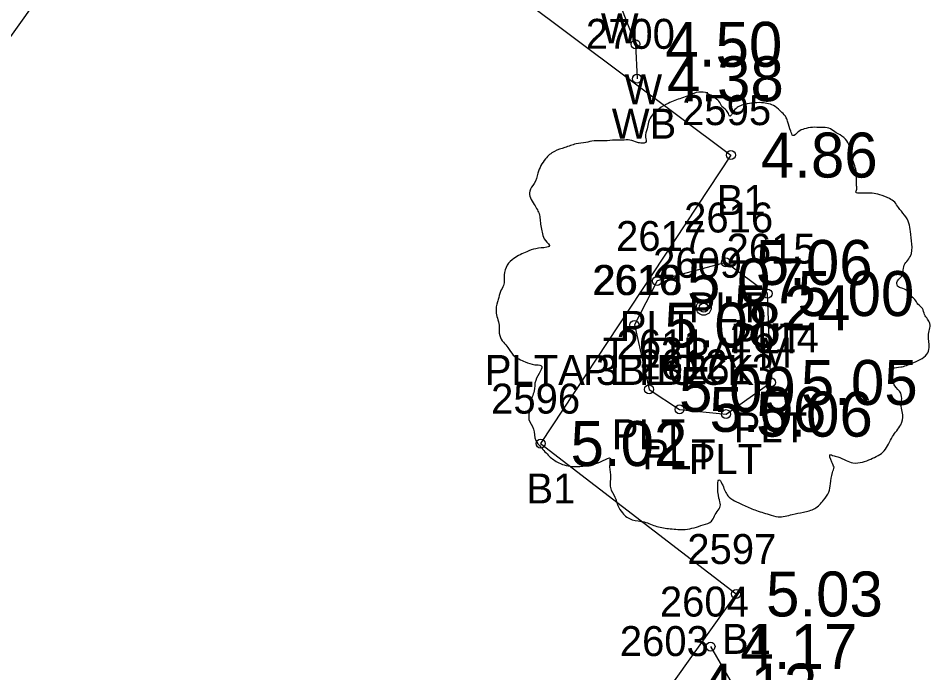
# Model space of a CAD drawing. Extents: x 2608598 to 2610682, y 641451 to 643526.
# Drawn here: x 2610088.05 to 2610118.53, y 642038.34 to 642060.19 of the extents above; entities that cross this region are included whole.
import ezdxf

# ---------------------------------------------------------------- set-up
doc = ezdxf.new("R2010")
doc.units = 0
for name, color, linetype in [('RD_EX_Bldg', 7, 'Continuous'), ('RD_EX_Bldg_txCode', 7, 'Continuous'), ('RD_EX_BldgApp', 7, 'Continuous'), ('RD_EX_BldgApp_txCode', 7, 'Continuous'), ('RD_EX_Conc_txCode', 7, 'Continuous'), ('RD_EX_Misc_txCode', 7, 'Continuous'), ('RD_EX_TX_Bldg_ELEV', 7, 'Continuous'), ('RD_EX_TX_BldgApp_ELEV', 7, 'Continuous'), ('RD_EX_TX_Conc_ELEV', 7, 'Continuous'), ('RD_EX_TX_Misc_ELEV', 7, 'Continuous'), ('RD_EX_TX_VEG_ELEV', 7, 'Continuous'), ('RD_EX_VEG', 7, 'Continuous'), ('RD_EX_VEG_txCode', 7, 'Continuous'), ('RD_SMD_Locator', 7, 'Continuous')]:
    doc.layers.add(name, color=color, linetype=linetype)

msp = doc.modelspace()

# ---------------------------------------------------------------- linework, layer by layer
at = {"layer": 'RD_EX_Bldg'}
msp.add_lwpolyline([(2610053.59, 642011.651), (2610094.327, 642068.736), (2610111.856, 642055.619), (2610105.498, 642045.99), (2610112.03, 642040.97), (2610078.047, 641993.35), (2610053.59, 642011.651)], dxfattribs=at)
at = {"layer": 'RD_EX_BldgApp'}
for points in [[(2610092.084, 642091.554), (2610090.066, 642087.454), (2610090.275, 642082.315), (2610090.442, 642078.076), (2610089.742, 642075.92), (2610088.411, 642073.718), (2610088.053, 642071.968), (2610088.518, 642070.915), (2610090.02, 642069.577), (2610091.576, 642069.053), (2610094.413, 642069.93), (2610096.189, 642069.722), (2610098.402, 642068.736), (2610102.184, 642065.332), (2610105.016, 642063.884), (2610107.881, 642061.348), (2610108.669, 642059.316), (2610108.72, 642058.165)], [(2610108.633, 642049.948), (2610109.123, 642047.799), (2610110.139, 642047.131), (2610111.694, 642046.972), (2610113.193, 642048.03), (2610113.081, 642050.997), (2610111.687, 642052.035), (2610109.389, 642051.418), (2610108.633, 642049.948)], [(2610111.175, 642039.216), (2610113.596, 642035.061)]]:
    msp.add_lwpolyline(points, dxfattribs=at)
at = {"layer": 'RD_EX_VEG'}
for centre, radius in [((2610110.949, 642050.524), 0.25), ((2610110.937, 642050.506), 0.0001)]:
    msp.add_circle(centre, radius, dxfattribs=at)
for points in [[(2610111.081, 642057.692), (2610110.781, 642057.717), (2610110.457, 642057.617), (2610110.207, 642057.517), (2610109.982, 642057.442), (2610109.757, 642057.342), (2610109.457, 642057.167), (2610109.232, 642056.967), (2610109.107, 642056.717), (2610109.057, 642056.492), (2610109.007, 642056.217), (2610109.007, 642056.042), (2610108.882, 642056.017), (2610108.732, 642056.042), (2610108.482, 642056.117), (2610108.232, 642056.117), (2610107.983, 642056.117), (2610107.633, 642056.092), (2610107.283, 642056.092), (2610107.008, 642056.042), (2610106.683, 642055.992), (2610106.308, 642055.867), (2610105.958, 642055.742), (2610105.659, 642055.493), (2610105.409, 642055.018), (2610105.284, 642054.668), (2610105.134, 642054.418), (2610105.284, 642053.968), (2610105.459, 642053.618), (2610105.484, 642053.418), (2610105.559, 642052.994), (2610105.659, 642052.769), (2610105.784, 642052.569), (2610105.709, 642052.544), (2610105.334, 642052.494), (2610105.034, 642052.394), (2610104.609, 642052.169), (2610104.384, 642051.944), (2610104.284, 642051.619), (2610104.259, 642051.269), (2610104.159, 642051.07), (2610104.084, 642050.795), (2610104.059, 642050.72), (2610104.009, 642050.395), (2610104.109, 642049.945), (2610104.134, 642049.595), (2610104.259, 642049.37), (2610104.409, 642049.195), (2610104.584, 642048.945), (2610104.984, 642048.721), (2610105.309, 642048.621), (2610105.509, 642048.596), (2610105.334, 642048.096), (2610105.284, 642047.746), (2610105.159, 642047.346), (2610105.159, 642047.271), (2610105.109, 642046.796), (2610105.259, 642046.471), (2610105.334, 642046.097), (2610105.509, 642045.872), (2610105.784, 642045.572), (2610106.108, 642045.347), (2610106.608, 642045.222), (2610107.008, 642045.247), (2610107.583, 642045.422), (2610107.833, 642045.497), (2610107.808, 642045.322), (2610107.833, 642044.947), (2610107.833, 642044.522), (2610107.983, 642044.198), (2610108.083, 642043.923), (2610108.232, 642043.673), (2610108.557, 642043.448), (2610108.957, 642043.373), (2610109.382, 642043.223), (2610109.832, 642043.148), (2610110.332, 642043.123), (2610110.931, 642043.273), (2610111.206, 642043.398), (2610111.306, 642043.573), (2610111.506, 642043.948), (2610111.456, 642044.173), (2610111.481, 642044.772), (2610111.581, 642044.597), (2610111.756, 642044.247), (2610112.256, 642043.948), (2610112.656, 642043.773), (2610113.13, 642043.623), (2610113.43, 642043.548), (2610113.905, 642043.623), (2610114.28, 642043.698), (2610114.655, 642043.823), (2610114.955, 642044.098), (2610115.129, 642044.372), (2610115.179, 642044.647), (2610115.254, 642045.022), (2610115.304, 642045.197)], [(2610115.304, 642045.197), (2610115.229, 642045.372), (2610115.179, 642045.622), (2610115.254, 642045.597), (2610115.429, 642045.547), (2610115.704, 642045.422), (2610115.929, 642045.347), (2610116.254, 642045.372), (2610116.529, 642045.472), (2610116.979, 642045.747), (2610117.254, 642046.222), (2610117.528, 642046.621), (2610117.603, 642046.946), (2610117.553, 642047.171), (2610117.528, 642047.671), (2610117.328, 642047.921), (2610117.278, 642048.046), (2610117.179, 642048.446), (2610117.254, 642048.496), (2610117.528, 642048.546), (2610117.903, 642048.671), (2610118.178, 642048.795), (2610118.403, 642048.97), (2610118.478, 642049.195), (2610118.453, 642049.595), (2610118.503, 642049.995), (2610118.428, 642050.145), (2610118.328, 642050.295), (2610118.253, 642050.495), (2610118.103, 642050.645), (2610118.003, 642050.795), (2610117.903, 642050.895), (2610117.778, 642051.045), (2610117.603, 642051.169), (2610117.453, 642051.219), (2610117.403, 642051.369), (2610117.553, 642051.569), (2610117.603, 642051.669), (2610117.628, 642051.894), (2610117.853, 642052.244), (2610117.903, 642052.644), (2610117.853, 642053.069), (2610117.803, 642053.344), (2610117.653, 642053.618), (2610117.453, 642053.868), (2610117.328, 642054.043), (2610117.154, 642054.168), (2610116.829, 642054.293), (2610116.579, 642054.343), (2610116.229, 642054.343), (2610116.029, 642054.393), (2610116.054, 642054.443), (2610116.054, 642054.593), (2610116.054, 642054.868), (2610115.979, 642055.318), (2610115.829, 642055.817), (2610115.829, 642055.842), (2610115.729, 642056.092), (2610115.504, 642056.292), (2610115.329, 642056.392), (2610115.129, 642056.517), (2610114.88, 642056.542), (2610114.58, 642056.542), (2610114.305, 642056.492), (2610114.105, 642056.392), (2610113.93, 642056.267), (2610113.855, 642056.417), (2610113.755, 642056.717), (2610113.705, 642056.867), (2610113.555, 642057.042), (2610113.33, 642057.242), (2610112.88, 642057.367), (2610112.256, 642057.292), (2610111.956, 642057.092), (2610111.806, 642056.917), (2610111.756, 642057.042), (2610111.556, 642057.242), (2610111.456, 642057.417), (2610111.281, 642057.542), (2610111.131, 642057.642), (2610111.031, 642057.692)]]:
    msp.add_spline(points, degree=3, dxfattribs=at)
at = {"layer": 'RD_SMD_Locator'}
for centre in [(2610108.669, 642059.316), (2610108.72, 642058.165), (2610111.856, 642055.619), (2610111.687, 642052.035), (2610109.389, 642051.418), (2610113.081, 642050.997), (2610110.949, 642050.524), (2610108.633, 642049.948), (2610108.633, 642049.948), (2610113.193, 642048.03), (2610109.123, 642047.799), (2610110.139, 642047.131), (2610111.694, 642046.972), (2610105.498, 642045.99), (2610112.03, 642040.97), (2610111.175, 642039.216)]:
    msp.add_circle(centre, 0.15, dxfattribs=at)

# ---------------------------------------------------------------- texts
at = {"layer": 'RD_EX_Bldg_txCode'}
for s, p in [('2595', (2610110.226, 642056.619)), ('B1', (2610111.384, 642053.619)), ('2596', (2610103.844, 642046.99)), ('B1', (2610105.026, 642043.99)), ('2597', (2610110.4, 642041.97)), ('B1', (2610111.557, 642038.97))]:
    msp.add_text(s, height=1, dxfattribs=at).set_placement(p)
at = {"layer": 'RD_EX_BldgApp_txCode'}
for s, p in [('2616', (2610110.293, 642053.035)), ('2617', (2610108.019, 642052.418)), ('2615', (2610111.711, 642051.997)), ('2610', (2610107.223, 642050.948)), ('2618', (2610107.263, 642050.948)), ('PLT', (2610110.443, 642050.035)), ('PLT', (2610108.145, 642049.418)), ('2614', (2610111.823, 642049.03)), ('PLT', (2610111.837, 642048.997)), ('2611', (2610108.037, 642048.799)), ('PLTA 3BLOCK', (2610103.633, 642047.948)), ('PLTB', (2610106.916, 642047.948)), ('2612', (2610108.769, 642048.131)), ('2613', (2610110.324, 642047.972)), ('PLT', (2610111.949, 642046.03)), ('PLT', (2610107.879, 642045.799)), ('PLT', (2610108.895, 642045.131)), ('PLT', (2610110.45, 642044.972))]:
    msp.add_text(s, height=1, dxfattribs=at).set_placement(p)
at = {"layer": 'RD_EX_Conc_txCode'}
msp.add_text('2603', height=1, dxfattribs=at).set_placement((2610108.144, 642038.898))
at = {"layer": 'RD_EX_Misc_txCode'}
for s, p in [('W', (2610107.511, 642059.348)), ('2700', (2610107.011, 642059.165)), ('W', (2610108.299, 642057.316)), ('WB', (2610107.877, 642056.165)), ('2604', (2610109.482, 642040.216))]:
    msp.add_text(s, height=1, dxfattribs=at).set_placement(p)
at = {"layer": 'RD_EX_TX_Bldg_ELEV'}
for s, p in [('4.86', (2610112.856, 642054.869)), ('5.02', (2610106.498, 642045.24)), ('5.03', (2610113.03, 642040.22))]:
    msp.add_text(s, height=1.5, dxfattribs=at).set_placement(p)
at = {"layer": 'RD_EX_TX_BldgApp_ELEV'}
for s, p in [('5.06', (2610112.687, 642051.285)), ('5.07', (2610110.389, 642050.668)), ('5.00', (2610114.081, 642050.247)), ('5.08', (2610109.633, 642049.198)), ('5.08', (2610109.633, 642049.198)), ('5.05', (2610114.193, 642047.28)), ('5.09', (2610110.123, 642047.049)), ('5.06', (2610111.139, 642046.381)), ('5.06', (2610112.694, 642046.222))]:
    msp.add_text(s, height=1.5, dxfattribs=at).set_placement(p)
at = {"layer": 'RD_EX_TX_Conc_ELEV'}
msp.add_text('4.12', height=1.5, dxfattribs=at).set_placement((2610110.837, 642037.148))
at = {"layer": 'RD_EX_TX_Misc_ELEV'}
for s, p in [('4.50', (2610109.669, 642058.566)), ('4.38', (2610109.72, 642057.415)), ('4.17', (2610112.175, 642038.466))]:
    msp.add_text(s, height=1.5, dxfattribs=at).set_placement(p)
at = {"layer": 'RD_EX_TX_VEG_ELEV'}
msp.add_text('5.24', height=1.5, dxfattribs=at).set_placement((2610111.949, 642049.774))
at = {"layer": 'RD_EX_VEG_txCode'}
for s, p in [('2609', (2610109.256, 642051.524)), ('T 12PALM', (2610107.579, 642048.524))]:
    msp.add_text(s, height=1, dxfattribs=at).set_placement(p)

doc.saveas('drawing.dxf')
